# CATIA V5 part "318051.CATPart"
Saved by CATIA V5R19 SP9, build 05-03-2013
Part number: 318051
Source: Unknown
Bounding box of the stored display mesh (mm): x -695.692 to 250, y 91 to 131, z 187.668 to 594
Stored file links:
  D:\16-SIL\kale oto\R19_V1\318051.CATPart
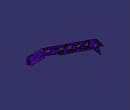
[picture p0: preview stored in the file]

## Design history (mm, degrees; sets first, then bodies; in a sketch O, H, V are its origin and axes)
Body1 "157\\122\\MANIFOLD_SOLID_BREP #72792" (main body)
  Solid1: solid without history
Body2 "241\\218\\MANIFOLD_SOLID_BREP #154205"
  Solid2: solid without history
Body3 "241\\219\\MANIFOLD_SOLID_BREP #153170"
  Solid3: solid without history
